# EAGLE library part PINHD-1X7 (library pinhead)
PIN HEADER
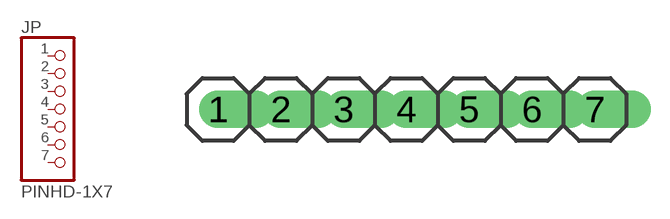
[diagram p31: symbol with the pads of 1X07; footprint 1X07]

Designator prefix JP

## PINHD-1X7  [1X07]
1  1  pas
2  2  pas
3  3  pas
4  4  pas
5  5  pas
6  6  pas
7  7  pas

## Footprint 1X07 (pad centres in mm)
PIN HEADER
drill 1.016 offset: 1 -7.62,0; 2 -5.08,0; 3 -2.54,0; 4 0,0; 5 2.54,0; 6 5.08,0; 7 7.62,0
